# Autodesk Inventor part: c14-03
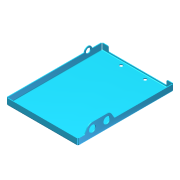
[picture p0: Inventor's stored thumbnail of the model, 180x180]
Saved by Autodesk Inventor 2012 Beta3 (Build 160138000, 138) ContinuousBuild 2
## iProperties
Created: 2011-01
Part Number: c14-03
Material: Steel, Mild
Document SubType Name: Sheet Metal
Designer: Beta-8540w
Density: 7.86 g/cm^3
Flat Pattern Width: 19.6226 cm
Flat Pattern Length: 22.2702 cm
Flat Pattern Area: 437.001 cm^2
Sheet Metal Rule: Steel - 16ga
Sheet Metal Width: 196.226 mm
Sheet Metal Length: 222.702 mm
Sheet Metal Area: 43700.096 mm^2
Author: Beta-8540w
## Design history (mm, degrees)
node "Face3"
  sketch "Sketch1"
    geometry: L1 (-75, 100)-(75, 100); L2 (75, 100)-(75, -100); L3 (75, -100)-(-75, -100); L4 (-75, -100)-(-75, 100); 3 further points
    constraints: 8 end point, 2 midpoint, 2 parallel, 1 horizontal, 1 horizontal alignment, 1 perpendicular, 1 vertical alignment
    dimensions: "d67" = 150 distance of L2.end L3.end; "d68" = 200 distance of L1.end L2.end
node "Flange3"
node "Face4"
  sketch "Sketch7"
    geometry: L1 (-10.952, 195.874)-(-10.952, 0) reference; L2 (0, 0)-(-10.952, 0) reference; L3 (-10.952, 11.937)-(-20.564, 17.596); L4 (-26.476, 27.937)-(-26.476, 57.937); L5 (-20.564, 68.278)-(-10.952, 73.937); L6 (0, -2.063)-(-10.952, -2.063) reference; L7 (1.524, 0.985)-(1.524, 194.889) reference; A1 r 12 centre (-14.476, 27.937) between (-26.476, 27.937) and (-20.564, 17.596); A2 r 12 centre (-14.476, 57.937) between (-20.564, 68.278) and (-26.476, 57.937); 1 further point
    constraints: 6 end point, 4 point on circle, 4 tangent, 2 centre point, 2 point on line, 1 equal length, 1 equal radius, 1 perpendicular
    dimensions: "d80" = 12 radius of A1; "d81" = 62 distance of L5.end L3.start; "d82" = 30 distance of A2.centre A1.centre; "d83" = 30 distance from line of L6 A1.centre; "d84" = 16 distance from line of L7 A1.centre
hole "Hole3" diameter "d92" = 14; stored, may be unused: countersink angle "d96" = 90 deg, drill point angle "d98" = 118 deg; dims "d93" = 6, "d94" = 4, "d95" = 2, "d97" = 1.524 (= Thickness), "d125" = 10, "d126" = 10
hole "Hole4" diameter "d101" = 14; stored, may be unused: countersink angle "d105" = 90 deg, drill point angle "d107" = 118 deg; dims "d102" = 6, "d103" = 4, "d104" = 2, "d106" = 1.524 (= Thickness), "d127" = 10, "d128" = 10
node "Face5"
  sketch "Sketch8"
    geometry: L1 (10.952, 0)-(10.952, 195.874) reference; L2 (0, 197.937)-(10.952, 197.937) reference; A1 r 8 centre (10.952, 167.937) between (10.952, 159.937) and (10.952, 175.937); 1 further point
    constraints: 3 point on line, 2 point on circle, 1 centre point
    dimensions: "d108" = 8 radius of A1; "d109" = 30 distance from line of L2 A1.centre
hole "Hole5" diameter "d117" = 10; stored, may be unused: countersink angle "d121" = 90 deg, drill point angle "d123" = 118 deg; dims "d115" = 10, "d116" = 10, "d118" = 6, "d119" = 4, "d120" = 2, "d122" = 1.524 (= Thickness)
feature "Corner Round2" dims "d124" = 2
sketch "Sketch9"
  geometry: L1 (0, -10.952)-(145.874, -10.952) reference; L2 (11.937, -0.952)-(133.937, -0.952); L3 (133.937, -0.952)-(133.937, -10.952); L4 (133.937, -10.952)-(11.937, -10.952); L5 (11.937, -10.952)-(11.937, -0.952); L6 (0.985, 3.048)-(144.889, 3.048) reference; 2 further points
  constraints: 8 end point, 2 midpoint, 2 parallel, 1 horizontal, 1 perpendicular
  dimensions: "d129" = 122 distance of L2.start L2.end; "d130" = 4 distance between parallel lines of L6 L2
cut "Cut1" sketch "Sketch9" dims "d131" = 1.524 (= Thickness), "d132" = 0
feature "Corner Round3" dims "d133" = 2
sketch "Sketch10"
  geometry: L1 (-25, 90)-(25, 90); L2 (25, 90)-(25, -90); L3 (25, -90)-(-25, -90); L4 (-25, -90)-(-25, 90); 3 further points
  constraints: 8 end point, 2 midpoint, 2 parallel, 1 horizontal, 1 horizontal alignment, 1 perpendicular, 1 vertical alignment
  dimensions: "d134" = 50 distance of L1.start L1.end; "d135" = 180 distance of L3.end L1.start
hole "Hole6" sketch "Sketch10" at (-25, 90), (25, -90), (25, 90), (-25, -90) diameter "d136" = 6.6; stored, may be unused: countersink angle "d140" = 90 deg, drill point angle "d142" = 118 deg; dims "d137" = 6, "d138" = 12.6, "d139" = 2, "d141" = 1.524 (= Thickness)
body "Solid3"
face "Plate5" dims "Thickness" = 1.524 (derived)
sketch "Sketch6"
  geometry: L1 (0, -14)-(150, -14); L2 (150, -14)-(150, 0); 2 other entities
  constraints: 4 end point, 4 other
face "Plate6" dims "d70" = 1.524 (= BendReliefWidth), "d71" = 0.762 (= BendReliefDepth), "d72" = 3.048 (= MinimumRemnant), "d73" = 1.524 (= BendRadius), "d74" = 14, "d75" = 90 deg, "d76" = 1.524 (= BendRadius), "d77" = 6.096 (= CornerReliefSize), "d78" = 0.762 (= GapSize), "d79" = 1.524 (= JacobiRadiusSize), "SeamGap" = 0.01, "Thickness" = 1.524 (derived)
bend "Bend5" dims "d70" = 1.524 (= BendReliefWidth), "d71" = 0.762 (= BendReliefDepth), "d72" = 3.048 (= MinimumRemnant), "d73" = 1.524 (= BendRadius), "d74" = 14, "d75" = 90 deg, "d76" = 1.524 (= BendRadius), "SeamGap" = 0.01, "Thickness" = 1.524 (derived)
feature "Corner3" dims "d74" = 14, "d75" = 90 deg, "d77" = 6.096 (= CornerReliefSize), "d78" = 0.762 (= GapSize), "d79" = 1.524 (= JacobiRadiusSize)
face "Plate7" dims "d85" = 1.524 (= BendRadius), "d86" = 1.524 (= BendReliefWidth), "d88" = 3.048 (= MinimumRemnant), "Thickness" = 1.524 (derived)
bend "Bend6" dims "d85" = 1.524 (= BendRadius), "d86" = 1.524 (= BendReliefWidth), "d87" = 0.762 (= BendReliefDepth), "d88" = 3.048 (= MinimumRemnant), "d89" = 1.524 (= BendRadius), "SeamGap" = 0.01, "Thickness" = 1.524 (derived)
face "Plate8" dims "d110" = 1.524 (= BendRadius), "d111" = 1.524 (= BendReliefWidth), "d113" = 3.048 (= MinimumRemnant), "Thickness" = 1.524 (derived)
bend "Bend7" dims "d110" = 1.524 (= BendRadius), "d111" = 1.524 (= BendReliefWidth), "d112" = 0.762 (= BendReliefDepth), "d113" = 3.048 (= MinimumRemnant), "d114" = 1.524 (= BendRadius), "SeamGap" = 0.01, "Thickness" = 1.524 (derived)
feature "Definition1"
other parameters: "BendRadius" = 1.524 (= Thickness), "BendReliefWidth" = 1.524 (= Thickness), "BendReliefDepth" = 0.762 (= 0.5 x Thickness), "CornerReliefSize" = 6.096 (= 4 x Thickness), "MinimumRemnant" = 3.048 (= 2 x Thickness), "TransitionRadius" = 1.524 (= BendRadius), "JacobiRadiusSize" = 1.524 (= BendRadius), "GapSize" = 0.762 (= 0.5 x Thickness), "d17" = 1.524 (= BendRadius), "d69" = 1.524 (= BendRadius), "BendRadius" = 1.524, "BendReliefDepth" = 0.762, "BendReliefWidth" = 1.524, "CornerReliefSize" = 6.096, "GapSize" = 0.762, "JacobiRadiusSize" = 1.524, "MinimumRemnant" = 3.048, "Thickness" = 1.524, "TransitionRadius" = 1.524
